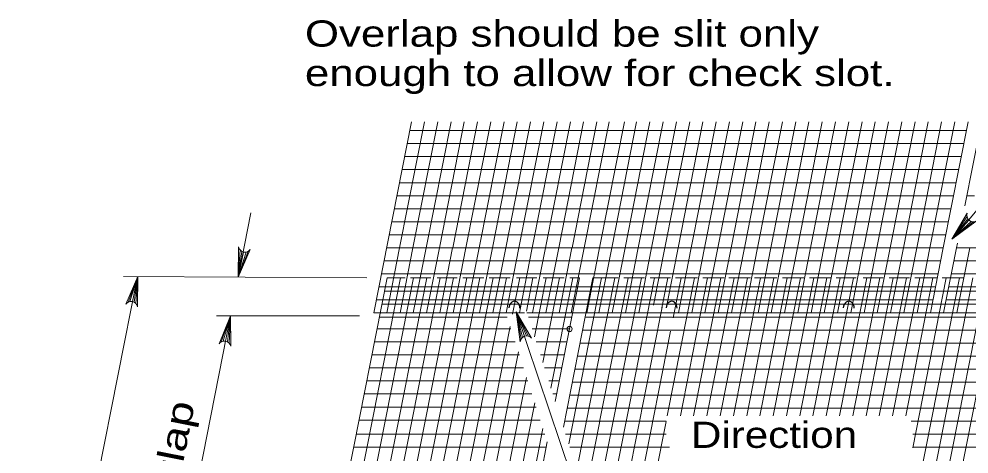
# Model space of a CAD drawing. Extents: x 1083.1 to 1117.1, y 719.4 to 741.4.
# Drawn here: x 1097.66 to 1103.31, y 729.91 to 732.5 of the extents above; entities that cross this region are included whole.
import ezdxf

# ---------------------------------------------------------------- set-up
doc = ezdxf.new("R2010")
doc.units = 0
doc.header["$LTSCALE"] = 0.062
doc.header["$PDMODE"] = 32
doc.header["$PDSIZE"] = 0.031
doc.layers.add('1', color=7, linetype='Continuous', lineweight=13)

msp = doc.modelspace()

# ---------------------------------------------------------------- linework, layer by layer
at = {"layer": '1'}
for p, q in [((1103.22208, 731.19675), (1104.004, 732.13775)), ((1099.77025, 730.75033), (1099.99458, 731.88508)), ((1099.92425, 731.13725), (1100.07217, 731.88508)), ((1100.00317, 731.13725), (1100.151, 731.88508)), ((1100.082, 731.13725), (1100.22983, 731.88508)), ((1100.16092, 731.13725), (1100.30875, 731.88508)), ((1100.23975, 731.13725), (1100.38758, 731.88508)), ((1100.31867, 731.13725), (1100.4665, 731.88508)), ((1100.3975, 731.13725), (1100.54533, 731.88508)), ((1100.47642, 731.13725), (1100.62425, 731.88508)), ((1100.55525, 731.13725), (1100.70317, 731.88508)), ((1100.63417, 731.13725), (1100.782, 731.88508)), ((1100.71308, 731.13725), (1100.86092, 731.88508)), ((1100.79192, 731.13725), (1100.93975, 731.88508)), ((1100.87083, 731.13725), (1101.01867, 731.88508)), ((1100.94967, 731.13725), (1101.0975, 731.88508)), ((1101.02217, 731.13725), (1101.17, 731.88508)), ((1101.11392, 731.13725), (1101.26175, 731.88508)), ((1101.18633, 731.13725), (1101.33425, 731.88508)), ((1101.26517, 731.13725), (1101.41308, 731.88508)), ((1101.34408, 731.13725), (1101.49192, 731.88508)), ((1101.42292, 731.13725), (1101.57083, 731.88508)), ((1101.50183, 731.13725), (1101.64967, 731.88508)), ((1101.58075, 731.13725), (1101.72858, 731.88508)), ((1101.65958, 731.13725), (1101.80742, 731.88508)), ((1101.7385, 731.13725), (1101.88633, 731.88508)), ((1101.81733, 731.13725), (1101.96517, 731.88508)), ((1101.89625, 731.13725), (1102.04408, 731.88508)), ((1101.97508, 731.13725), (1102.123, 731.88508)), ((1102.054, 731.13725), (1102.20183, 731.88508)), ((1102.13283, 731.13725), (1102.28075, 731.88508)), ((1102.21175, 731.13725), (1102.35958, 731.88508)), ((1102.29067, 731.13725), (1102.4385, 731.88508)), ((1102.3695, 731.13725), (1102.51733, 731.88508)), ((1102.44842, 731.13725), (1102.59625, 731.88508)), ((1102.52725, 731.13725), (1102.67508, 731.88508)), ((1102.60617, 731.13725), (1102.754, 731.88508)), ((1102.685, 731.13725), (1102.83292, 731.88508)), ((1102.76392, 731.13725), (1102.91175, 731.88508)), ((1102.84275, 731.13725), (1102.99067, 731.88508)), ((1102.92167, 731.13725), (1103.0695, 731.88508)), ((1103.00058, 731.13725), (1103.14842, 731.88508)), ((1103.07942, 731.13725), (1103.22725, 731.88508)), ((1103.15833, 731.13725), (1103.30617, 731.88508)), ((1103.2865, 731.3865), (1103.385, 731.88508)), ((1103.296, 731.83358), (1099.98467, 731.83358)), ((1103.28067, 731.75617), (1099.96933, 731.75617)), ((1103.26542, 731.67883), (1099.954, 731.67883)), ((1103.25008, 731.60142), (1099.93875, 731.60142)), ((1103.23475, 731.52408), (1099.92342, 731.52408)), ((1103.2195, 731.44675), (1099.90808, 731.44675)), ((1103.34525, 731.44675), (1103.29842, 731.44675)), ((1103.20417, 731.36933), (1099.89283, 731.36933)), ((1098.96567, 730.9695), (1099.03983, 731.34467)), ((1103.2995, 731.32133), (1103.20917, 731.18708)), ((1103.30417, 731.30992), (1103.20917, 731.18708)), ((1103.18892, 731.292), (1099.8775, 731.292)), ((1103.3115, 731.30108), (1103.20917, 731.18708)), ((1103.32408, 731.29358), (1103.20917, 731.18708)), ((1103.33592, 731.29125), (1103.20917, 731.18708)), ((1103.17367, 731.21458), (1099.86217, 731.21458)), ((1103.23717, 731.13725), (1103.24233, 731.16325)), ((1098.97567, 731.123), (1098.96417, 730.96167)), ((1098.98533, 731.11542), (1098.96417, 730.96167)), ((1099.02217, 731.115), (1098.96417, 730.96167)), ((1098.99608, 731.11142), (1098.96417, 730.96167)), ((1099.01075, 731.11117), (1098.96417, 730.96167)), ((1099.84667, 731.13725), (1103.15817, 731.13725)), ((1099.84683, 731.13725), (1101.02908, 731.13725)), ((1099.84758, 730.75033), (1099.92408, 731.13725)), ((1099.9265, 730.75033), (1100.003, 731.13725)), ((1100.00542, 730.75033), (1100.08183, 731.13725)), ((1100.08425, 730.75033), (1100.16075, 731.13725)), ((1100.16317, 730.75033), (1100.23958, 731.13725)), ((1100.242, 730.75033), (1100.3185, 731.13725)), ((1100.32092, 730.75033), (1100.39733, 731.13725)), ((1100.39975, 730.75033), (1100.47625, 731.13725)), ((1100.47867, 730.75033), (1100.55508, 731.13725)), ((1100.5575, 730.75033), (1100.634, 731.13725)), ((1100.63642, 730.75033), (1100.71292, 731.13725)), ((1100.71533, 730.75033), (1100.79175, 731.13725)), ((1100.79417, 730.75033), (1100.87067, 731.13725)), ((1100.87308, 730.75033), (1100.9495, 731.13725)), ((1100.9455, 730.75033), (1101.022, 731.13725)), ((1101.03733, 730.75033), (1101.11375, 731.13725)), ((1101.10967, 730.75033), (1101.18617, 731.13725)), ((1101.18858, 730.75033), (1101.265, 731.13725)), ((1101.26742, 730.75033), (1101.34392, 731.13725)), ((1101.34633, 730.75033), (1101.42283, 731.13725)), ((1101.434, 730.79483), (1101.50167, 731.13725)), ((1101.51317, 730.79617), (1101.58058, 731.13725)), ((1101.583, 730.75033), (1101.65942, 731.13725)), ((1101.66183, 730.75033), (1101.73833, 731.13725)), ((1101.74075, 730.75033), (1101.81717, 731.13725)), ((1101.81958, 730.75033), (1101.89608, 731.13725)), ((1101.8985, 730.75033), (1101.97492, 731.13725)), ((1101.97733, 730.75033), (1102.05383, 731.13725)), ((1102.05625, 730.75033), (1102.13267, 731.13725)), ((1102.13508, 730.75033), (1102.21158, 731.13725)), ((1102.214, 730.75033), (1102.2905, 731.13725)), ((1102.29292, 730.75033), (1102.36933, 731.13725)), ((1102.37175, 730.75033), (1102.44825, 731.13725)), ((1102.45067, 730.75033), (1102.52708, 731.13725)), ((1102.5295, 730.75033), (1102.606, 731.13725)), ((1102.60842, 730.75033), (1102.68483, 731.13725)), ((1102.68725, 730.75033), (1102.76375, 731.13725)), ((1102.76617, 730.75033), (1102.84258, 731.13725)), ((1102.845, 730.75033), (1102.9215, 731.13725)), ((1102.92392, 730.75033), (1103.00042, 731.13725)), ((1103.00283, 730.75033), (1103.07925, 731.13725)), ((1103.08167, 730.75033), (1103.15817, 731.13725)), ((1103.16058, 730.75033), (1103.237, 731.13725)), ((1103.237, 731.13725), (1103.71033, 731.13725)), ((1103.23942, 730.75033), (1103.31592, 731.13725)), ((1099.83133, 731.05983), (1103.14283, 731.05983)), ((1099.83158, 731.05983), (1101.01375, 731.05983)), ((1103.22167, 731.05983), (1103.695, 731.05983)), ((1099.81617, 730.9825), (1103.12758, 730.9825)), ((1099.81625, 730.9825), (1100.99842, 730.9825)), ((1103.20642, 730.9825), (1103.67975, 730.9825)), ((1097.65958, 727.40708), (1098.36458, 730.96625)), ((1099.72925, 730.95708), (1098.28125, 730.96625)), ((1098.30833, 730.81308), (1098.366, 730.96658)), ((1098.31975, 730.81692), (1098.366, 730.96658)), ((1098.33442, 730.81675), (1098.366, 730.96658)), ((1098.34517, 730.81275), (1098.366, 730.96658)), ((1098.35483, 730.80517), (1098.366, 730.96658)), ((1099.22433, 727.39792), (1099.92858, 730.95708)), ((1099.30317, 727.39792), (1100.00742, 730.95708)), ((1099.38208, 727.39792), (1100.08633, 730.95708)), ((1099.461, 727.39792), (1100.16525, 730.95708)), ((1099.52283, 729.30358), (1099.84967, 730.95708)), ((1099.53983, 727.39792), (1100.24408, 730.95708)), ((1099.61875, 727.39792), (1100.323, 730.95708)), ((1099.69758, 727.39792), (1100.40183, 730.95708)), ((1099.7765, 727.39792), (1100.48075, 730.95708)), ((1099.84967, 730.95708), (1099.9565, 730.95708)), ((1099.85533, 727.39792), (1100.55958, 730.95708)), ((1099.98908, 730.95708), (1100.11008, 730.95708)), ((1100.14717, 730.95708), (1100.267, 730.95708)), ((1100.30083, 730.95708), (1100.42583, 730.95708)), ((1100.45775, 730.95708), (1100.58167, 730.95708)), ((1100.59592, 730.74192), (1100.6385, 730.95708)), ((1100.619, 730.95708), (1100.73942, 730.95708)), ((1100.6785, 730.76058), (1100.71733, 730.95708)), ((1100.72717, 730.60783), (1100.79625, 730.95708)), ((1100.77583, 730.45475), (1100.87517, 730.95708)), ((1100.77767, 730.95708), (1100.90208, 730.95708)), ((1100.82458, 730.30192), (1100.954, 730.95708)), ((1100.84992, 730.22225), (1100.99517, 730.95708)), ((1100.89858, 730.06942), (1101.074, 730.95708)), ((1100.93025, 729.96983), (1101.12542, 730.95708)), ((1100.93642, 730.95708), (1100.99517, 730.95708)), ((1100.97892, 729.817), (1101.20433, 730.95708)), ((1101.074, 730.95708), (1101.22475, 730.95708)), ((1101.07625, 729.5115), (1101.36217, 730.95708)), ((1101.11392, 730.10058), (1101.28325, 730.95708)), ((1101.25833, 730.95708), (1101.38017, 730.95708)), ((1101.30375, 730.26158), (1101.441, 730.95708)), ((1101.41383, 730.95708), (1101.53475, 730.95708)), ((1101.48483, 730.77958), (1101.51992, 730.95708)), ((1101.51558, 730.13783), (1101.6775, 730.95708)), ((1101.55208, 730.72067), (1101.59883, 730.95708)), ((1101.56583, 730.95708), (1101.69725, 730.95708)), ((1101.59442, 730.13783), (1101.75642, 730.95708)), ((1101.67333, 730.13783), (1101.83525, 730.95708)), ((1101.7275, 730.95708), (1101.85525, 730.95708)), ((1101.75217, 730.13783), (1101.91417, 730.95708)), ((1101.83108, 730.13783), (1101.993, 730.95708)), ((1101.88292, 730.95708), (1102.01242, 730.95708)), ((1101.90992, 730.13783), (1102.07192, 730.95708)), ((1101.98892, 730.13783), (1102.15075, 730.95708)), ((1102.03575, 730.95708), (1102.169, 730.95708)), ((1102.06775, 730.13783), (1102.22967, 730.95708)), ((1102.14658, 730.13783), (1102.3085, 730.95708)), ((1102.20175, 730.95708), (1102.3285, 730.95708)), ((1102.2255, 730.13783), (1102.38742, 730.95708)), ((1102.30433, 730.13783), (1102.46633, 730.95708)), ((1102.36183, 730.95708), (1102.48708, 730.95708)), ((1102.38325, 730.13783), (1102.54517, 730.95708)), ((1102.46217, 730.13783), (1102.62408, 730.95708)), ((1102.52217, 730.95708), (1102.641, 730.95708)), ((1102.541, 730.13783), (1102.70292, 730.95708)), ((1102.61983, 730.13783), (1102.78183, 730.95708)), ((1102.68108, 730.95708), (1102.8005, 730.95708)), ((1102.69875, 730.13783), (1102.86067, 730.95708)), ((1102.77758, 730.13783), (1102.93958, 730.95708)), ((1102.78825, 727.39792), (1103.49175, 730.95708)), ((1102.83617, 730.95708), (1102.9575, 730.95708)), ((1102.83858, 728.45092), (1103.334, 730.95708)), ((1102.83867, 728.05233), (1103.41283, 730.95708)), ((1102.8565, 730.13783), (1103.01842, 730.95708)), ((1102.93533, 730.13783), (1103.09733, 730.95708)), ((1102.97675, 729.94775), (1103.17625, 730.95708)), ((1102.97675, 729.54875), (1103.25508, 730.95708)), ((1102.9885, 730.95708), (1103.11933, 730.95708)), ((1103.15258, 730.95708), (1103.27658, 730.95708)), ((1099.80083, 730.90508), (1103.11225, 730.90508)), ((1099.80092, 730.90508), (1100.98308, 730.90508)), ((1099.83433, 730.87967), (1103.63425, 730.87967)), ((1103.19108, 730.90508), (1103.66442, 730.90508)), ((1099.78558, 730.82775), (1100.96775, 730.82775)), ((1099.78558, 730.82775), (1103.097, 730.82775)), ((1099.81917, 730.80233), (1103.61892, 730.80233)), ((1103.17592, 730.82775), (1103.64917, 730.82775)), ((1099.77025, 730.75033), (1100.66725, 730.75033)), ((1101.46192, 728.25383), (1100.61817, 730.75558)), ((1100.66733, 730.61058), (1100.61817, 730.75558)), ((1100.65467, 730.60325), (1100.61817, 730.75558)), ((1100.64675, 730.59408), (1100.61817, 730.75558)), ((1100.67867, 730.61258), (1100.61817, 730.75558)), ((1100.69083, 730.61108), (1100.61817, 730.75558)), ((1100.68175, 730.75033), (1103.16058, 730.75033)), ((1101.17367, 729.2055), (1101.48558, 730.7835)), ((1103.16058, 730.75033), (1103.63383, 730.75033)), ((1098.91858, 730.73125), (1098.3185, 727.69617)), ((1099.6855, 730.73125), (1098.83525, 730.73125)), ((1098.86283, 730.577), (1098.91858, 730.73125)), ((1098.87417, 730.58108), (1098.91858, 730.73125)), ((1098.88883, 730.581), (1098.91858, 730.73125)), ((1098.89967, 730.57725), (1098.91858, 730.73125)), ((1098.9095, 730.56975), (1098.91858, 730.73125)), ((1099.80383, 730.725), (1100.56358, 730.725)), ((1100.68983, 730.725), (1100.94975, 730.725)), ((1101.5485, 730.725), (1101.02817, 730.725)), ((1103.60367, 730.725), (1101.55058, 730.725)), ((1099.78983, 730.65392), (1100.5865, 730.65392)), ((1099.93425, 727.39792), (1100.5815, 730.66925)), ((1100.7125, 730.65392), (1100.93525, 730.65392)), ((1101.54025, 730.64758), (1101.01283, 730.64758)), ((1101.22225, 729.05292), (1101.53617, 730.64)), ((1103.58833, 730.64758), (1101.54025, 730.64758)), ((1099.7745, 730.57658), (1100.61142, 730.57658)), ((1100.73708, 730.57658), (1100.92, 730.57658)), ((1100.01308, 727.39792), (1100.63042, 730.5175)), ((1101.48375, 730.57025), (1100.9975, 730.57025)), ((1101.28233, 730.55358), (1101.28233, 730.55367)), ((1103.573, 730.57025), (1101.48375, 730.57025)), ((1099.75917, 730.49917), (1100.63633, 730.49917)), ((1100.76175, 730.49917), (1100.90467, 730.49917)), ((1101.43567, 730.49283), (1100.98217, 730.49283)), ((1103.55775, 730.49283), (1101.43567, 730.49283)), ((1099.74392, 730.42183), (1100.66125, 730.42183)), ((1100.78642, 730.42183), (1100.88942, 730.42183)), ((1101.38992, 730.4155), (1100.96683, 730.4155)), ((1103.5425, 730.4155), (1101.38992, 730.4155)), ((1100.092, 727.39792), (1100.67925, 730.36583)), ((1099.72858, 730.34442), (1100.68617, 730.34442)), ((1100.811, 730.34442), (1100.87417, 730.34442)), ((1101.35017, 730.33808), (1100.9515, 730.33808)), ((1103.52717, 730.33808), (1101.35017, 730.33808)), ((1099.71325, 730.26708), (1100.71108, 730.26708)), ((1100.83567, 730.26708), (1100.85883, 730.26708)), ((1101.30808, 730.26075), (1100.93617, 730.26075)), ((1101.12475, 729.35892), (1101.3035, 730.26167)), ((1103.51192, 730.26075), (1101.30808, 730.26075)), ((1099.698, 730.18967), (1100.736, 730.18967)), ((1100.53975, 729.26017), (1100.72825, 730.21375)), ((1101.27867, 730.18333), (1100.92083, 730.18333)), ((1103.49658, 730.18333), (1101.27867, 730.18333)), ((1099.68267, 730.11233), (1100.76092, 730.11233)), ((1101.258, 730.106), (1100.9055, 730.106)), ((1101.02758, 729.66417), (1101.11492, 730.10608)), ((1101.50892, 730.106), (1101.258, 730.106)), ((1101.27092, 728.9), (1101.50892, 730.10408)), ((1103.48133, 730.106), (1102.96767, 730.106)), ((1099.66633, 730.02858), (1100.78783, 730.02858)), ((1100.25067, 727.39792), (1100.77708, 730.06192)), ((1101.2395, 730.02858), (1100.91158, 730.02858)), ((1101.50892, 730.02858), (1101.2395, 730.02858)), ((1103.466, 730.02858), (1102.97675, 730.02858)), ((1099.65108, 729.95125), (1100.79658, 729.95125)), ((1100.29158, 727.39792), (1100.80258, 729.98292)), ((1101.216, 729.95125), (1100.93617, 729.95125)), ((1101.52983, 729.95125), (1101.216, 729.95125)), ((1103.45067, 729.95125), (1102.97675, 729.95125))]:
    msp.add_line(p, q, dxfattribs=at)
for points in [[(1103.35375, 731.29525), (1103.20917, 731.18708), (1103.30108, 731.3425)], [(1099.03567, 731.12733), (1098.96417, 730.96167), (1098.96642, 731.14208)], [(1098.29483, 730.80067), (1098.366, 730.96658), (1098.36408, 730.78608)], [(1100.6415, 730.57658), (1100.61817, 730.75558), (1100.70858, 730.59933)], [(1098.8495, 730.5645), (1098.91858, 730.73125), (1098.91892, 730.55075)]]:
    msp.add_lwpolyline(points, dxfattribs=at)
for centre, start, end in [((1103.33691, 731.32953), 160.19314, 296.01927), ((1099.00401, 731.14873), 190.05629, 325.88241), ((1098.32656, 730.77939), 10.18114, 146.00727), ((1098.88149, 730.54362), 10.90504, 146.73117), ((1100.67965, 730.57445), 40.82036, 176.64649)]:
    msp.add_arc(centre, 0.0382, start, end, dxfattribs=at)
at = {"layer": '1', "lineweight": 25}
for centre in [(1100.60707, 730.77798), (1101.54204, 730.77798), (1102.59613, 730.77798)]:
    msp.add_ellipse(centre, major_axis=(0.00099, 0.04097), ratio=0.78812, start_param=4.7123995, end_param=7.8539922, dxfattribs=at)
at = {"layer": '1'}
msp.add_point((1100.93525, 730.65392), dxfattribs=at)

# ---------------------------------------------------------------- texts
for s, width, p in [('Overlap should be slit only', 1.25, (1099.36058, 732.33325)), ('enough to allow for check slot.', 1.25, (1099.36058, 732.09858)), ('Direction', 1.2, (1101.65783, 729.9465))]:
    msp.add_text(s, height=0.156, dxfattribs=dict(at, width=width)).set_placement(p)
at = {"layer": '1', "width": 1.3}
msp.add_text('4" [100] min. overlap', height=0.156, rotation=78.819, dxfattribs=at).set_placement((1098.2255, 727.77817))

doc.saveas('drawing.dxf')
